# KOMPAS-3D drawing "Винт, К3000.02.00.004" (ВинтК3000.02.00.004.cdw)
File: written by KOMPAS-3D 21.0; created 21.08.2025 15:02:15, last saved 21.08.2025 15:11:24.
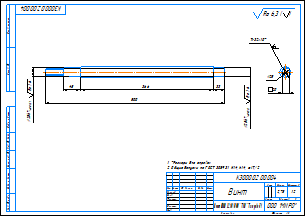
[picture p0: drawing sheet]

Sheet 1: A3, landscape

Document properties: Автор: admin; Знак неуказанной шероховатости: 4; Параметр неуказанной шероховатости: Ra 6,3; Масса: 2.777487

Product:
- Part/product: Винт  | designation К3000.02.00.004
    Масса: 2.777487

Title block, sheet 1: Наименование: Винт; designation: К3000.02.00.004; Материал: Винт ШВП 3210 ("ООО" "ТКП" "Техпривод"); Масса: 2,78; Количество листов документа: 1; organisation: ООО "МИРО"; Форматы листов документа: A3; stored path: C:\Users\ShavarinML\Desktop\Стапель\2D\ВинтК3000.02.00.004.cdw

Views: Спереди 1, Спереди, Проекционный вид 2, Вид:1
Referenced files in C:\Users\ShavarinML\Desktop\Стапель\Задняя бабака\Из трубы\Ролики\: Винт.m3d
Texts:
  Ra 1,6
  Tr32x10
  Ra 6,3
  Ra 6,3 ( )
  К3000.02.00.004 Винт
Dimensions and other numbers on the sheet: 33; 366; 48; 500; 25; 20; 1:2; 1; 2,78

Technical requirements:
  *Размеры для справок.
  Общие допуски по ГОСТ 30893.1: H14, h14,   IT/2.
